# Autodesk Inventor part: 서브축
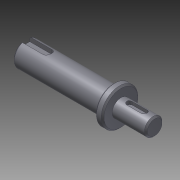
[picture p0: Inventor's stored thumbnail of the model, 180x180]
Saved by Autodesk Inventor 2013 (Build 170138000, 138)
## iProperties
Created: 2018-09
Part Number: 서브축
Document SubType Name: Modeling
Density: 1 g/cm^3
Material: 강철, 연강
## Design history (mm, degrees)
sketch "스케치1"
  geometry: L1 (-18.818, -7)-(-18.818, 7) reference; L2 (-41.331, -13.5)-(-41.331, 13.5) reference; L3 (-46.5, 12.249)-(-46.5, -12.249) reference; L4 (-18.331, 0)-(-106.5, 0); L5 (-18.331, 0)-(-18.331, -6); L6 (-18.331, -6)-(-41.331, -6); L7 (-41.331, -12.5)-(-46.5, -12.5); L8 (-46.5, -8.5)-(-106.5, -8.5); L9 (-106.5, -8.5)-(-106.5, 0); L10 (-46.5, -8.5)-(-46.5, -12.5); L11 (-41.331, -6)-(-41.331, -12.5); 2 further points
  constraints: 17 end point, 5 point on line, 3 parallel, 3 perpendicular, 2 collinear, 1 midpoint
  dimensions: "d0" = 23 distance between parallel lines of L2 L5; "d1" = 12 diameter of L6 L4; "d2" = 25 diameter of L7 L4; "d3" = 17 diameter of L8 L4; "d4" = 60 distance of L8.start L8.end
revolve "회전1" sketch "스케치1" stored, may be unused: angle "d5" = 90 deg
chamfer "모따기1" distance "d6" = 1; stored, may be unused: second distance "d7" = 2, angle "d8" = 45 deg
node "작업 평면1"
sketch "스케치2"
  geometry: L1 (11.5, 5)-(11.5, -5) reference; L2 (-5.5, -2)-(4.5, -2); L3 (4.5, 2)-(-5.5, 2); A1 r 2 centre (4.5, 0) between (4.5, -2) and (4.5, 2); A2 r 2 centre (-5.5, 0) between (-5.5, 2) and (-5.5, -2); 2 further points
  constraints: 4 end point, 4 point on circle, 4 tangent, 2 centre point, 1 horizontal alignment, 1 midpoint, 1 parallel, 1 perpendicular
  dimensions: "d9" = 4 distance between parallel lines of L2 L3; "d10" = 14 dimension on A1 A2; "d11" = 5 distance edge to line of A1 L1
extrude "돌출1" cut sketch "스케치2" distance "d12" = 2.5; taper "d13" = 0 deg
node "작업 평면2"
sketch "스케치3"
  geometry: L1 (-30, -7.5)-(-30, 7.5) reference; L2 (-30, 3)-(-15, 3); L3 (-15, -3)-(-30, -3); A1 r 3 centre (-15, 0) between (-15, -3) and (-15, 3); 2 further points
  constraints: 4 end point, 2 perpendicular, 2 point on circle, 2 point on line, 2 tangent, 1 centre point, 1 horizontal alignment, 1 midpoint
  dimensions: "d14" = 6 distance between parallel lines of L3 L2; "d15" = 18 dimension on A1 L1
extrude "돌출2" cut sketch "스케치3" distance "d16" = 3.5; taper "d17" = 0 deg
node "솔리드1"
node "참조1"
node "참조2"
node "참조3"
